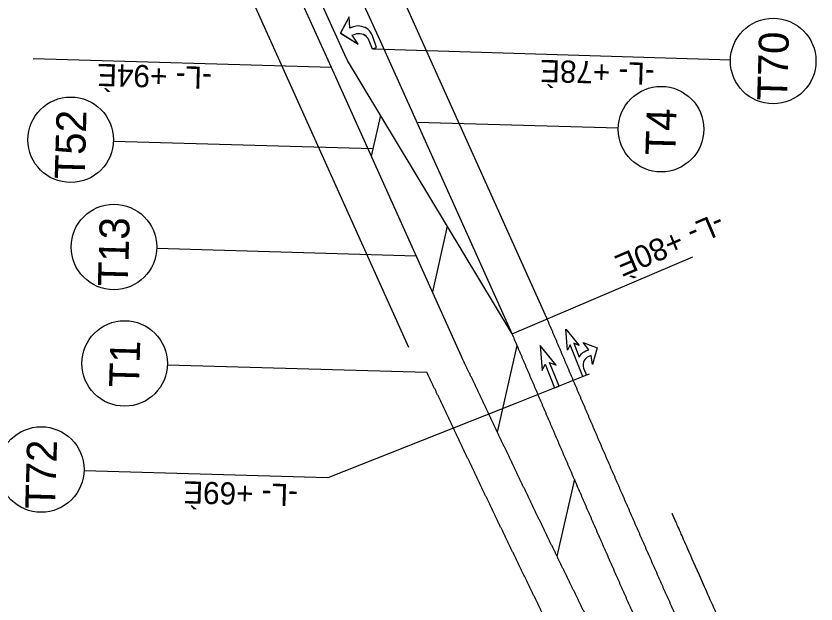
# Model space of a CAD drawing. Extents: x 1657109 to 2100937, y 684916 to 883211.
# Drawn here: x 2097693.3 to 2097945.7, y 685543.3 to 685728.9 of the extents above; entities that cross this region are included whole.
import ezdxf

# ---------------------------------------------------------------- set-up
doc = ezdxf.new("R2010")
doc.units = 0
for name, color, linetype in [('Old_Level_12', 7, 'Continuous'), ('Old_Level_63', 7, 'Continuous'), ('Prop CMT Pvmt Gravel', 7, 'Continuous'), ('Prop Conc 1ft 6in Curb and Gutter', 7, 'Continuous'), ('Prop Conc 2ft 6in Curb and Gutter', 7, 'Continuous'), ('Prop Conc Curb and Gutter', 7, 'Continuous'), ('Prop EOT', 7, 'Continuous'), ('Prop Guardrail Anchor Unit CELL', 7, 'Continuous'), ('Prop Paved Shoulder', 7, 'Continuous'), ('Prop Sign E Chevron Right', 7, 'Continuous'), ('Scratch_Level_1', 7, 'Continuous'), ('Scratch_Level_5', 7, 'Continuous')]:
    doc.layers.add(name, color=color, linetype=linetype)

# ---------------------------------------------------------------- blocks, each defined once
blk = doc.blocks.new('SRARR')
at = {"layer": 'Old_Level_63'}
blk.add_lwpolyline([(0, 0.5), (8.667, 0.5), (7.667, 1.583), (12.75, 0), (7.667, -1.583), (8.667, -0.5), (4.895, -0.5), (5.26, -0.958), (5.468, -1.31), (5.628, -1.759), (5.708, -2.127), (5.772, -2.592), (5.75, -3.417), (8, -2.75), (5.417, -5.583), (1.917, -2.917), (4.167, -3.417), (4.155, -2.768), (4.138, -2.384), (4.042, -1.999), (3.866, -1.663), (3.674, -1.326), (3.322, -0.99), (2.889, -0.734), (2.425, -0.574), (1.896, -0.493), (0, -0.5)], close=True, dxfattribs=at)
blk.add_lwpolyline([(0, 0.5), (8.667, 0.5), (7.667, 1.583), (12.75, 0), (7.667, -1.583), (8.667, -0.5), (4.895, -0.5), (5.26, -0.958), (5.468, -1.31), (5.628, -1.759), (5.708, -2.127), (5.772, -2.592), (5.75, -3.417), (8, -2.75), (5.417, -5.583), (1.917, -2.917), (4.167, -3.417), (4.155, -2.768), (4.138, -2.384), (4.042, -1.999), (3.866, -1.663), (3.674, -1.326), (3.322, -0.99), (2.889, -0.734), (2.425, -0.574), (1.896, -0.493), (0, -0.5)], close=True, dxfattribs=at)

msp = doc.modelspace()

# ---------------------------------------------------------------- linework, layer by layer
at = {"layer": 'Old_Level_12'}
for p, q in [((2097808.31, 685697.48), (2097805.4, 685684.68)), ((2097829.39, 685662.5), (2097824.69, 685641.82)), ((2097845.21, 685597.5), (2097851.44, 685624.84)), ((2097869.5, 685582.64), (2097863.98, 685558.4))]:
    msp.add_line(p, q, dxfattribs=at)
at = {"layer": 'Prop CMT Pvmt Gravel'}
for p, q in [((2097792.84, 685712.58), (2097698.67, 685715.32)), ((2097819.76, 685695.41), (2097883.36, 685693.56)), ((2097724.05, 685689.42), (2097805.94, 685687.03)), ((2097737.68, 685655.57), (2097819.57, 685653.19)), ((2097849.86, 685628.54), (2097906.87, 685652.85)), ((2097741.07, 685618.81), (2097822.96, 685616.43))]:
    msp.add_line(p, q, dxfattribs=at)
for points in [[(2097806.03, 685718.57), (2097918.75, 685715.06)], [(2097874.11, 685615.82), (2097873.31, 685615.5), (2097851.25, 685606.7), (2097791.7, 685583.09), (2097714.75, 685585.31)]]:
    msp.add_lwpolyline(points, dxfattribs=at)
for centre in [(2097932.24, 685714.67), (2097896.85, 685693.16), (2097710.55, 685689.81), (2097724.19, 685655.96), (2097727.57, 685619.2), (2097701.25, 685585.71)]:
    msp.add_circle(centre, 13.5, dxfattribs=at)
at = {"layer": 'Prop Conc 1ft 6in Curb and Gutter'}
msp.add_line((2097808.82, 685719.73), (2097771.08, 685803.58), dxfattribs=at)
at = {"layer": 'Prop Conc 2ft 6in Curb and Gutter'}
msp.add_line((2097849.86, 685628.54), (2097808.82, 685719.73), dxfattribs=at)
at = {"layer": 'Prop Conc Curb and Gutter'}
for p, q in [((2097797.05, 685716.63), (2097760.13, 685798.66)), ((2097792.84, 685712.58), (2097755.12, 685796.4)), ((2097797.87, 685714.8), (2097797.05, 685716.63))]:
    msp.add_line(p, q, dxfattribs=at)
at = {"layer": 'Prop EOT'}
msp.add_line((2097860.8, 685633.46), (2097782.02, 685808.51), dxfattribs=at)
for points in [[(2097889.71, 685566.26), (2097889.31, 685567.17), (2097888.92, 685568.07), (2097888.52, 685568.98), (2097888.13, 685569.88), (2097887.73, 685570.79), (2097887.33, 685571.69), (2097886.94, 685572.6), (2097886.55, 685573.5), (2097886.15, 685574.41), (2097885.76, 685575.31), (2097885.36, 685576.22), (2097884.97, 685577.12), (2097884.57, 685578.03), (2097884.18, 685578.93), (2097883.79, 685579.84), (2097883.39, 685580.74), (2097883, 685581.65), (2097882.61, 685582.55), (2097882.22, 685583.46), (2097881.82, 685584.37), (2097881.43, 685585.27), (2097881.04, 685586.18), (2097880.65, 685587.08), (2097880.26, 685587.99), (2097879.86, 685588.9), (2097879.47, 685589.8), (2097879.08, 685590.71), (2097878.69, 685591.62), (2097878.3, 685592.52), (2097877.91, 685593.43), (2097877.52, 685594.34), (2097877.13, 685595.24), (2097876.74, 685596.15), (2097876.35, 685597.06), (2097875.96, 685597.96), (2097875.57, 685598.87), (2097875.18, 685599.78), (2097874.79, 685600.69), (2097874.4, 685601.59), (2097874.01, 685602.5), (2097873.62, 685603.41), (2097873.23, 685604.32), (2097872.85, 685605.22), (2097872.46, 685606.13), (2097872.07, 685607.04), (2097871.68, 685607.95), (2097871.29, 685608.85), (2097870.91, 685609.76), (2097870.52, 685610.67), (2097870.13, 685611.58), (2097869.74, 685612.49), (2097869.35, 685613.4), (2097868.96, 685614.32), (2097868.58, 685615.23), (2097868.19, 685616.14), (2097867.8, 685617.05), (2097867.41, 685617.96), (2097867.02, 685618.87), (2097866.63, 685619.79), (2097866.24, 685620.7), (2097865.85, 685621.61), (2097865.47, 685622.52), (2097865.08, 685623.43), (2097864.69, 685624.35), (2097864.3, 685625.26), (2097863.91, 685626.17), (2097863.52, 685627.08), (2097863.13, 685627.99), (2097862.74, 685628.9), (2097862.36, 685629.82), (2097861.97, 685630.73), (2097861.58, 685631.64), (2097860.8, 685633.46)], [(2097919.51, 685499.54), (2097919.1, 685500.44), (2097918.69, 685501.34), (2097918.28, 685502.24), (2097917.87, 685503.14), (2097917.46, 685504.04), (2097917.06, 685504.93), (2097916.65, 685505.83), (2097916.24, 685506.73), (2097915.83, 685507.63), (2097915.42, 685508.53), (2097915.02, 685509.43), (2097914.61, 685510.33), (2097914.2, 685511.23), (2097913.8, 685512.13), (2097913.39, 685513.03), (2097912.98, 685513.93), (2097912.58, 685514.83), (2097912.17, 685515.73), (2097911.76, 685516.63), (2097911.36, 685517.53), (2097910.95, 685518.43), (2097910.55, 685519.33), (2097910.14, 685520.23), (2097909.74, 685521.13), (2097909.33, 685522.03), (2097908.93, 685522.94), (2097908.52, 685523.84), (2097908.12, 685524.74), (2097907.71, 685525.64), (2097907.31, 685526.54), (2097906.9, 685527.44), (2097906.5, 685528.34), (2097906.1, 685529.24), (2097905.69, 685530.14), (2097905.29, 685531.05), (2097904.89, 685531.95), (2097904.49, 685532.85), (2097904.08, 685533.75), (2097903.68, 685534.65), (2097903.28, 685535.55), (2097902.88, 685536.46), (2097902.47, 685537.36), (2097902.07, 685538.26), (2097901.67, 685539.16), (2097901.27, 685540.06), (2097900.87, 685540.97), (2097900.47, 685541.87), (2097900.07, 685542.77), (2097899.67, 685543.67), (2097899.26, 685544.58), (2097898.86, 685545.48), (2097898.46, 685546.38), (2097898.06, 685547.29), (2097897.66, 685548.19), (2097897.27, 685549.09), (2097896.87, 685549.99), (2097896.47, 685550.9), (2097896.07, 685551.8), (2097895.67, 685552.7), (2097895.27, 685553.61), (2097894.87, 685554.51), (2097894.47, 685555.41), (2097894.08, 685556.32), (2097893.68, 685557.22), (2097893.28, 685558.13), (2097892.88, 685559.03), (2097892.48, 685559.93), (2097892.09, 685560.84), (2097891.69, 685561.74), (2097891.29, 685562.65), (2097890.9, 685563.55), (2097890.5, 685564.45), (2097890.1, 685565.36), (2097889.71, 685566.26)]]:
    msp.add_spline(points, degree=3, dxfattribs=at)
at = {"layer": 'Prop Guardrail Anchor Unit CELL'}
for points in [[(2097854.68, 685550.08), (2097854.25, 685550.98), (2097853.81, 685551.87), (2097853.38, 685552.77), (2097852.94, 685553.66), (2097852.51, 685554.56), (2097852.07, 685555.45), (2097851.64, 685556.35), (2097851.21, 685557.25), (2097850.77, 685558.14), (2097850.34, 685559.04), (2097849.91, 685559.93), (2097849.47, 685560.83), (2097849.04, 685561.72), (2097848.61, 685562.62), (2097848.17, 685563.52), (2097847.74, 685564.41), (2097847.31, 685565.31), (2097846.88, 685566.21), (2097846.45, 685567.1), (2097846.01, 685568), (2097845.58, 685568.9), (2097845.15, 685569.79), (2097844.72, 685570.69), (2097844.29, 685571.59), (2097843.86, 685572.48), (2097843.43, 685573.38), (2097843, 685574.28), (2097842.57, 685575.18), (2097842.14, 685576.07), (2097841.71, 685576.97), (2097841.28, 685577.87), (2097840.85, 685578.77), (2097840.42, 685579.66), (2097839.99, 685580.56), (2097839.56, 685581.46), (2097839.13, 685582.36), (2097838.7, 685583.26), (2097838.28, 685584.15), (2097837.85, 685585.05), (2097837.42, 685585.95), (2097836.99, 685586.85), (2097836.56, 685587.75), (2097836.14, 685588.65), (2097835.71, 685589.54), (2097835.28, 685590.44), (2097834.86, 685591.34), (2097834.43, 685592.24), (2097834, 685593.14), (2097833.58, 685594.04), (2097833.15, 685594.94), (2097832.73, 685595.83), (2097832.3, 685596.73), (2097831.88, 685597.62), (2097831.45, 685598.52), (2097831.03, 685599.41), (2097830.6, 685600.31), (2097830.18, 685601.21), (2097829.75, 685602.1), (2097829.33, 685603), (2097828.9, 685603.89), (2097828.48, 685604.79), (2097828.05, 685605.68), (2097827.63, 685606.58), (2097827.2, 685607.47), (2097826.78, 685608.37), (2097826.35, 685609.27), (2097825.93, 685610.16), (2097825.51, 685611.06), (2097825.08, 685611.95), (2097824.66, 685612.85), (2097824.23, 685613.74), (2097823.81, 685614.64), (2097822.96, 685616.43)], [(2097887.35, 685484.11), (2097886.9, 685485), (2097886.46, 685485.89), (2097886.01, 685486.78), (2097885.56, 685487.66), (2097885.11, 685488.55), (2097884.67, 685489.44), (2097884.22, 685490.33), (2097883.77, 685491.22), (2097883.33, 685492.11), (2097882.88, 685493), (2097882.44, 685493.89), (2097881.99, 685494.78), (2097881.54, 685495.67), (2097881.1, 685496.55), (2097880.65, 685497.44), (2097880.21, 685498.33), (2097879.76, 685499.22), (2097879.32, 685500.11), (2097878.87, 685501), (2097878.43, 685501.89), (2097877.98, 685502.78), (2097877.54, 685503.67), (2097877.1, 685504.56), (2097876.65, 685505.45), (2097876.21, 685506.34), (2097875.76, 685507.23), (2097875.32, 685508.12), (2097874.88, 685509.02), (2097874.43, 685509.91), (2097873.99, 685510.8), (2097873.55, 685511.69), (2097873.11, 685512.58), (2097872.66, 685513.47), (2097872.22, 685514.36), (2097871.78, 685515.25), (2097871.34, 685516.14), (2097870.9, 685517.04), (2097870.46, 685517.93), (2097870.01, 685518.82), (2097869.57, 685519.71), (2097869.13, 685520.6), (2097868.69, 685521.49), (2097868.25, 685522.39), (2097867.81, 685523.28), (2097867.37, 685524.17), (2097866.93, 685525.06), (2097866.49, 685525.96), (2097866.05, 685526.85), (2097865.61, 685527.74), (2097865.17, 685528.63), (2097864.73, 685529.53), (2097864.29, 685530.42), (2097863.85, 685531.31), (2097863.42, 685532.2), (2097862.98, 685533.1), (2097862.54, 685533.99), (2097862.1, 685534.88), (2097861.66, 685535.78), (2097861.23, 685536.67), (2097860.79, 685537.56), (2097860.35, 685538.46), (2097859.91, 685539.35), (2097859.48, 685540.25), (2097859.04, 685541.14), (2097858.6, 685542.03), (2097858.17, 685542.93), (2097857.73, 685543.82), (2097857.29, 685544.72), (2097856.86, 685545.61), (2097856.42, 685546.51), (2097855.99, 685547.4), (2097855.55, 685548.29), (2097855.12, 685549.19), (2097854.68, 685550.08)]]:
    msp.add_spline(points, degree=3, dxfattribs=at)
for points, degree in [([(2097900.7, 685571.08), (2097900.55, 685571.42), (2097900.4, 685571.77), (2097900.37, 685571.83)], 2), ([(2097930.43, 685504.52), (2097930.27, 685504.86), (2097930.12, 685505.21), (2097929.88, 685505.72), (2097929.78, 685505.94), (2097929.68, 685506.16), (2097929.64, 685506.24), (2097929.62, 685506.29), (2097929.56, 685506.42), (2097929.21, 685507.19), (2097928.23, 685509.35), (2097926.03, 685514.19), (2097921.65, 685523.88), (2097915.43, 685537.74), (2097909.26, 685551.61), (2097904.97, 685561.34), (2097902.84, 685566.21), (2097901.92, 685568.29), (2097901.31, 685569.68), (2097901.01, 685570.38), (2097900.7, 685571.08)], 3)]:
    msp.add_open_spline(points, degree=degree, dxfattribs=at)
at = {"layer": 'Prop Paved Shoulder'}
for points in [[(2097805.66, 685718.47), (2097807.07, 685718.98), (2097805.75, 685722.62), (2097805.47, 685723.28), (2097805.2, 685723.76), (2097804.82, 685724.25), (2097804.4, 685724.63), (2097804.03, 685724.9), (2097803.46, 685725.22), (2097802.99, 685725.4), (2097802.45, 685725.58), (2097801.78, 685725.71), (2097801.27, 685725.73), (2097800.6, 685725.69), (2097799.74, 685725.51), (2097798.61, 685725.1), (2097798.4, 685728.61), (2097795.72, 685723.52), (2097801.27, 685719.94), (2097799.42, 685722.86), (2097800.36, 685723.2), (2097800.89, 685723.36), (2097801.43, 685723.4), (2097801.87, 685723.36), (2097802.47, 685723.25), (2097802.9, 685723.11), (2097803.44, 685722.78), (2097803.9, 685722.34), (2097804.29, 685721.88), (2097804.68, 685721.17)], [(2097805.66, 685718.47), (2097807.07, 685718.98), (2097805.75, 685722.62), (2097805.47, 685723.28), (2097805.2, 685723.76), (2097804.82, 685724.25), (2097804.4, 685724.63), (2097804.03, 685724.9), (2097803.46, 685725.22), (2097802.99, 685725.4), (2097802.45, 685725.58), (2097801.78, 685725.71), (2097801.27, 685725.73), (2097800.6, 685725.69), (2097799.74, 685725.5), (2097798.61, 685725.09), (2097798.4, 685728.6), (2097795.72, 685723.51), (2097801.27, 685719.94), (2097799.42, 685722.86), (2097800.36, 685723.2), (2097800.89, 685723.36), (2097801.43, 685723.4), (2097801.87, 685723.36), (2097802.46, 685723.25), (2097802.9, 685723.1), (2097803.44, 685722.77), (2097803.9, 685722.34), (2097804.29, 685721.88), (2097804.68, 685721.17)]]:
    msp.add_lwpolyline(points, close=True, dxfattribs=at)
at = {"layer": 'Prop Sign E Chevron Right'}
msp.add_line((2097817.26, 685624.22), (2097510.8, 686305.14), dxfattribs=at)
at = {"layer": 'Scratch_Level_1'}
for p, q in [((2097849.86, 685628.54), (2097797.87, 685714.8)), ((2097833.9, 685621.36), (2097792.84, 685712.58))]:
    msp.add_line(p, q, dxfattribs=at)
for points in [[(2097878.81, 685561.23), (2097878.42, 685562.14), (2097878.02, 685563.04), (2097877.62, 685563.95), (2097877.23, 685564.86), (2097876.83, 685565.76), (2097876.43, 685566.67), (2097876.04, 685567.58), (2097875.64, 685568.49), (2097875.25, 685569.39), (2097874.85, 685570.3), (2097874.46, 685571.21), (2097874.06, 685572.12), (2097873.67, 685573.02), (2097873.27, 685573.93), (2097872.88, 685574.84), (2097872.48, 685575.75), (2097872.09, 685576.65), (2097871.7, 685577.56), (2097871.3, 685578.47), (2097870.91, 685579.38), (2097870.52, 685580.29), (2097870.12, 685581.19), (2097869.73, 685582.1), (2097869.34, 685583.01), (2097868.94, 685583.92), (2097868.55, 685584.83), (2097868.16, 685585.74), (2097867.77, 685586.65), (2097867.38, 685587.55), (2097866.98, 685588.46), (2097866.59, 685589.37), (2097866.2, 685590.28), (2097865.81, 685591.19), (2097865.42, 685592.1), (2097865.03, 685593.01), (2097864.64, 685593.92), (2097864.25, 685594.83), (2097863.86, 685595.74), (2097863.47, 685596.65), (2097863.08, 685597.55), (2097862.69, 685598.46), (2097862.3, 685599.37), (2097861.91, 685600.28), (2097861.52, 685601.19), (2097861.13, 685602.1), (2097860.74, 685603.01), (2097860.35, 685603.92), (2097859.97, 685604.83), (2097859.58, 685605.74), (2097859.19, 685606.66), (2097858.8, 685607.57), (2097858.41, 685608.48), (2097858.02, 685609.39), (2097857.63, 685610.3), (2097857.24, 685611.21), (2097856.86, 685612.13), (2097856.47, 685613.04), (2097856.08, 685613.95), (2097855.69, 685614.86), (2097855.3, 685615.77), (2097854.91, 685616.68), (2097854.52, 685617.6), (2097854.13, 685618.51), (2097853.75, 685619.42), (2097853.36, 685620.33), (2097852.97, 685621.24), (2097852.58, 685622.16), (2097852.19, 685623.07), (2097851.8, 685623.98), (2097851.41, 685624.89), (2097851.02, 685625.8), (2097850.64, 685626.71), (2097849.86, 685628.54)], [(2097865.57, 685555.12), (2097865.14, 685556.01), (2097864.71, 685556.9), (2097864.27, 685557.79), (2097863.84, 685558.69), (2097863.41, 685559.58), (2097862.97, 685560.47), (2097862.54, 685561.37), (2097862.11, 685562.26), (2097861.68, 685563.15), (2097861.24, 685564.05), (2097860.81, 685564.94), (2097860.38, 685565.83), (2097859.95, 685566.73), (2097859.52, 685567.62), (2097859.08, 685568.52), (2097858.65, 685569.41), (2097858.22, 685570.3), (2097857.79, 685571.2), (2097857.36, 685572.09), (2097856.93, 685572.99), (2097856.5, 685573.88), (2097856.07, 685574.78), (2097855.64, 685575.67), (2097855.21, 685576.57), (2097854.78, 685577.46), (2097854.35, 685578.36), (2097853.92, 685579.25), (2097853.49, 685580.15), (2097853.06, 685581.04), (2097852.63, 685581.94), (2097852.2, 685582.83), (2097851.78, 685583.73), (2097851.35, 685584.62), (2097850.92, 685585.52), (2097850.49, 685586.42), (2097850.06, 685587.31), (2097849.64, 685588.21), (2097849.21, 685589.1), (2097848.78, 685590), (2097848.35, 685590.9), (2097847.93, 685591.79), (2097847.5, 685592.69), (2097847.07, 685593.58), (2097846.65, 685594.48), (2097846.22, 685595.38), (2097845.79, 685596.27), (2097845.37, 685597.17), (2097844.94, 685598.07), (2097844.52, 685598.97), (2097844.09, 685599.86), (2097843.67, 685600.76), (2097843.24, 685601.65), (2097842.82, 685602.55), (2097842.39, 685603.44), (2097841.97, 685604.34), (2097841.54, 685605.23), (2097841.12, 685606.13), (2097840.7, 685607.03), (2097840.27, 685607.92), (2097839.85, 685608.82), (2097839.42, 685609.71), (2097839, 685610.61), (2097838.57, 685611.5), (2097838.15, 685612.4), (2097837.72, 685613.3), (2097837.3, 685614.19), (2097836.87, 685615.09), (2097836.45, 685615.98), (2097836.02, 685616.88), (2097835.6, 685617.77), (2097835.17, 685618.67), (2097834.75, 685619.56), (2097833.9, 685621.36)], [(2097908.69, 685494.35), (2097908.28, 685495.25), (2097907.87, 685496.15), (2097907.46, 685497.05), (2097907.05, 685497.95), (2097906.64, 685498.86), (2097906.23, 685499.76), (2097905.82, 685500.66), (2097905.41, 685501.56), (2097905, 685502.46), (2097904.6, 685503.36), (2097904.19, 685504.26), (2097903.78, 685505.17), (2097903.37, 685506.07), (2097902.96, 685506.97), (2097902.55, 685507.87), (2097902.15, 685508.77), (2097901.74, 685509.68), (2097901.33, 685510.58), (2097900.92, 685511.48), (2097900.52, 685512.38), (2097900.11, 685513.29), (2097899.7, 685514.19), (2097899.3, 685515.09), (2097898.89, 685515.99), (2097898.49, 685516.9), (2097898.08, 685517.8), (2097897.67, 685518.7), (2097897.27, 685519.61), (2097896.86, 685520.51), (2097896.46, 685521.41), (2097896.05, 685522.32), (2097895.65, 685523.22), (2097895.24, 685524.12), (2097894.84, 685525.03), (2097894.44, 685525.93), (2097894.03, 685526.83), (2097893.63, 685527.74), (2097893.22, 685528.64), (2097892.82, 685529.55), (2097892.42, 685530.45), (2097892.01, 685531.35), (2097891.61, 685532.26), (2097891.21, 685533.16), (2097890.81, 685534.07), (2097890.4, 685534.97), (2097890, 685535.88), (2097889.6, 685536.78), (2097889.2, 685537.68), (2097888.8, 685538.59), (2097888.39, 685539.49), (2097887.99, 685540.4), (2097887.59, 685541.3), (2097887.19, 685542.21), (2097886.79, 685543.11), (2097886.39, 685544.02), (2097885.99, 685544.92), (2097885.59, 685545.83), (2097885.19, 685546.73), (2097884.79, 685547.64), (2097884.39, 685548.55), (2097883.99, 685549.45), (2097883.59, 685550.36), (2097883.19, 685551.26), (2097882.79, 685552.17), (2097882.39, 685553.07), (2097882, 685553.98), (2097881.6, 685554.89), (2097881.2, 685555.79), (2097880.8, 685556.7), (2097880.4, 685557.6), (2097880.01, 685558.51), (2097879.61, 685559.42), (2097879.21, 685560.32), (2097878.81, 685561.23)], [(2097898.17, 685489.3), (2097897.72, 685490.19), (2097897.28, 685491.07), (2097896.83, 685491.96), (2097896.39, 685492.85), (2097895.94, 685493.73), (2097895.49, 685494.62), (2097895.05, 685495.51), (2097894.6, 685496.39), (2097894.16, 685497.28), (2097893.71, 685498.17), (2097893.27, 685499.05), (2097892.82, 685499.94), (2097892.38, 685500.83), (2097891.93, 685501.72), (2097891.49, 685502.6), (2097891.04, 685503.49), (2097890.6, 685504.38), (2097890.15, 685505.27), (2097889.71, 685506.15), (2097889.27, 685507.04), (2097888.82, 685507.93), (2097888.38, 685508.82), (2097887.94, 685509.7), (2097887.49, 685510.59), (2097887.05, 685511.48), (2097886.61, 685512.37), (2097886.17, 685513.26), (2097885.73, 685514.15), (2097885.28, 685515.03), (2097884.84, 685515.92), (2097884.4, 685516.81), (2097883.96, 685517.7), (2097883.52, 685518.59), (2097883.08, 685519.48), (2097882.63, 685520.37), (2097882.19, 685521.26), (2097881.75, 685522.15), (2097881.31, 685523.04), (2097880.87, 685523.93), (2097880.43, 685524.82), (2097879.99, 685525.71), (2097879.55, 685526.59), (2097879.11, 685527.48), (2097878.67, 685528.37), (2097878.24, 685529.26), (2097877.8, 685530.15), (2097877.36, 685531.05), (2097876.92, 685531.94), (2097876.48, 685532.83), (2097876.04, 685533.72), (2097875.6, 685534.61), (2097875.17, 685535.5), (2097874.73, 685536.39), (2097874.29, 685537.28), (2097873.85, 685538.17), (2097873.42, 685539.06), (2097872.98, 685539.95), (2097872.54, 685540.84), (2097872.1, 685541.74), (2097871.67, 685542.63), (2097871.23, 685543.52), (2097870.8, 685544.41), (2097870.36, 685545.3), (2097869.92, 685546.19), (2097869.49, 685547.08), (2097869.05, 685547.98), (2097868.62, 685548.87), (2097868.18, 685549.76), (2097867.75, 685550.65), (2097867.31, 685551.55), (2097866.88, 685552.44), (2097866.44, 685553.33), (2097866.01, 685554.22), (2097865.57, 685555.12)]]:
    msp.add_spline(points, degree=3, dxfattribs=at)
at = {"layer": 'Scratch_Level_5'}
msp.add_lwpolyline([(2097859.34, 685616.93), (2097860.29, 685618.92), (2097863.26, 685611.49), (2097864.65, 685612.05), (2097861.69, 685619.48), (2097863.75, 685618.69), (2097858.72, 685624.89)], close=True, dxfattribs=at)
msp.add_lwpolyline([(2097859.34, 685616.93), (2097860.29, 685618.92), (2097863.26, 685611.49), (2097864.65, 685612.05), (2097861.69, 685619.48), (2097863.75, 685618.69), (2097858.72, 685624.89)], close=True, dxfattribs=at)

# ---------------------------------------------------------------- block references
at = {"layer": 'Prop CMT Pvmt Gravel', "xscale": 1.25, "yscale": 1.2499999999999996, "rotation": 111.75168141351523}
msp.add_blockref('SRARR', (2097872.73, 685615.27), dxfattribs=at)

# ---------------------------------------------------------------- texts
at = {"layer": 'Prop CMT Pvmt Gravel'}
for s, height, rotation, p in [('T70', 9.45, 88.3348, (2097936.6, 685702.04)), ('-L- +94È', 7, 178.4251, (2097755.17, 685712.8)), ('-L- +78È', 7, 178.4251, (2097894.93, 685714.06)), ('T52', 9.45, 88.3348, (2097714.92, 685677.25)), ('T4', 9.45, 88.3348, (2097901.34, 685684.82)), ('-L- +80È', 7, 203.1841, (2097914.93, 685667.08)), ('T13', 9.45, 88.3348, (2097728.55, 685643.46)), ('T1', 9.45, 88.3348, (2097732.08, 685611.57)), ('T72', 9.45, 88.3348, (2097705.62, 685573.15)), ('-L- +69È', 7, 178.4251, (2097782.36, 685581.04))]:
    msp.add_text(s, height=height, rotation=rotation, dxfattribs=at).set_placement(p)

doc.saveas('drawing.dxf')
